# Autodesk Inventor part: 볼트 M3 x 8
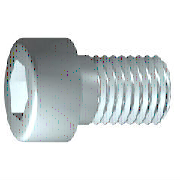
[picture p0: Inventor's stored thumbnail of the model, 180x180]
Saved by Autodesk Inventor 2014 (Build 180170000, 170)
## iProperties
IsCustomPart: 0
Created: 2012-02
Part Number: 볼트 M3 x 8
Material: 스테인리스강
Description: 6각 소켓 머리 캡 나사
Document SubType Name: Modeling
Standard: ISO 4762
Designer: mduedu
Standard Revision: Fourth edition 2004-03-01
Standards Organization: ISO
Language: ko-KR
Size Designation: M3 x 8
Categories: <MemberInstance><Categories><Category DisplayName="조임쇠" InternalName="e4da775c-781d-43d5-af7c-5136215cf5a6" Mnemonic="FSTN"><Category DisplayName="볼트" InternalN
Density: 8.08 g/cm^3
Appearance: 반광택
Author: mduedu
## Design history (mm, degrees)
sketch "스케치1"
  geometry: L1 (-0.867, 0)-(8, 0); L2 (8, 0)-(8, 1.5); L3 (8, 1.5)-(1.25, 1.5); L4 (1.25, 1.5)-(0.943, 1.5); L5 (0.943, 1.5)-(0, 1.5); L6 (0, 1.5)-(0, 2.75); L7 (0, 2.75)-(-3, 2.75); L8 (-3, 2.75)-(-3, 1.443); L9 (-3, 1.443)-(-1.7, 1.443); L10 (-1.7, 1.443)-(-0.867, 0); L11 (-5.2, 0)-(10.2, 0) reference; L12 (0, -0.55)-(0, 3.3) reference; L13 (1.25, 1.5)-(0, 1.5)
  constraints: 22 end point, 6 parallel, 2 collinear, 2 perpendicular, 1 horizontal, 1 point on line
  dimensions: "d1" = 6.75 distance from line of L3.end L2 (= GEL); "d2" = 0.30683 distance of L4.end L3.end (computed from GAL); "d3" = 3 distance between parallel lines of L8 L6 (= KOH); "d4" = 1.3 distance of L8.end L9.end (= INTI); "d5" = 60 deg angle of L10 L1; "d6" = 3 diameter of L3 L1 (= GD); "d7" = 3 diameter of L5 L1 (= BDM); "d8" = 2.88675 diameter of L9 L1 (= 1.1547 x SW); "d9" = 5.5 diameter of L7 L1 (= KOD); "d26" = 8 distance between parallel lines of L12 L2 (= NLG)
revolve "본체" sketch "스케치1" stored, may be unused: angle "d10" = 90 deg
sketch "스케치2"
  geometry: L1 (0, -3.85)-(0, 3.85) reference; L2 (-3.85, 0)-(3.85, 0) reference; L3 (1.443, 0)-(0.722, -1.25); L4 (0.722, -1.25)-(-0.722, -1.25); L5 (-0.722, -1.25)-(-1.443, 0); L6 (-1.443, 0)-(-0.722, 1.25); L7 (-0.722, 1.25)-(0.722, 1.25); L8 (0.722, 1.25)-(1.443, 0); 2 further points
  constraints: 12 end point, 1 coincident, 1 horizontal alignment, 1 point on line, 12 other
extrude "슬롯" join sketch "스케치2" stored distance "d11" = 10; taper "d12" = 0 deg
workplane "Work Plane1"
fillet "Fillet2" dims "d30" = 0.1 (= R)
body "Solid1"
fillet "모깎기1" dims "d17" = 0.3 (= RR)
feature "스레드" dims "d13" = 6.75 (= GEL), "d14" = 0
chamfer "모따기1" distance "d15" = 0.30673 (= -0.5 x SPD + 0.5 x GD); stored, may be unused: second distance "d16" = 0.30673 (= GUL), angle "d27" = 45 deg
other parameters: "GD" = 3 [user parameter; used in 2 equation terms], "NLG" = 8 [user parameter; used in 1 equation term], "GEL" = 6.75 [user parameter; used in 2 equation terms], "KOD" = 5.5 [user parameter; used in 1 equation term], "KOH" = 3 [user parameter; used in 1 equation term], "INTI" = 1.3 [user parameter; used in 1 equation term], "GAL" = 0.30673 (= 0.61345 x PTC) [user parameter; used in 1 equation term], "GUL" = 0.30673 (= 0.61345 x PTC) [user parameter; used in 1 equation term], "BDM" = 3 (= NND) [user parameter; used in 1 equation term], "SW" = 2.5 [user parameter; used in 2 equation terms], "RR" = 0.3 [user parameter; used in 1 equation term], "SPD" = 2.38655 (= NND - 1.2269 x PTC) [user parameter; used in 1 equation term], "d19" = 0, "d28" = 0, "d29" = 0, "R" = 0.1 [user parameter; used in 1 equation term], "TOA" = 30 deg [user parameter], "GD1" = 2.38655 (= THREADDIA - 1.2269 x PTC) [user parameter], "THREADDIA" = 3 [user parameter; used in 1 equation term], "FAWI" = 45 deg [user parameter], "PTC" = 0.5 [user parameter; used in 5 equation terms], "NND" = 3 [user parameter; used in 2 equation terms], "E0" = 2.8875 (= 1.155 x SW) [user parameter]
